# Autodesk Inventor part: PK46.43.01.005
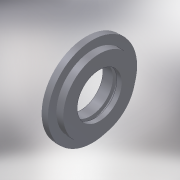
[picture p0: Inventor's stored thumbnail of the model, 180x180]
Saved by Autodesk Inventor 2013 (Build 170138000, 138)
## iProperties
Shininess: 64.0
Length Units: 11269
Angle Units: 11279
Time Units: 11290
Mass Units: 11283
Length Display Precision: 3
Angle Display Precision: 2
Compacted: True
Part Number: PK46.43.01.005
Document SubType Name: Modeling
Created: 2004-11
Material: Сталь высокопрочная низколегированная
Designer: ELarisa
Manufacturer: Standard
Standards Organization: Custom
Density: 7.84 g/cm^3
Density: 0.0
Volumn: 0.0
Area: 0.0
PropertySet Name: Model Information
Control State: 0
Master: False
Checked Out: False
Checked Out Date: 2008-10-09
Last Check In Date: 2008-10-09
Author: ELarisa
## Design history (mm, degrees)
sketch "Эскиз1"
  geometry: L1 (-25.184, 0.049)-(-25.184, 45.049); L2 (-25.184, 45.049)-(-16.184, 45.049); L3 (-16.184, 45.049)-(-16.184, 71.049); L4 (-16.184, 71.049)-(-6.184, 71.049); L5 (-6.184, 71.049)-(-6.184, 57.549); L6 (-6.184, 57.549)-(4.816, 57.549); L7 (4.816, 57.549)-(4.816, 0.049); L8 (4.816, 0.049)-(-25.184, 0.049); L9 (-25.184, 35.549)-(-9.184, 35.549); L10 (-9.184, 35.549)-(-9.184, 42.099); L11 (-9.184, 42.099)-(-2.884, 42.099); L12 (-2.884, 42.099)-(-2.884, 35.549); L13 (-2.884, 35.549)-(4.816, 35.549)
  constraints: 26 end point, 9 parallel, 3 perpendicular, 2 point on line, 1 collinear, 1 vertical
  dimensions: "d0" = 30 distance of L7.end L1.start; "d1" = 14 distance between parallel lines of L7 L10; "d2" = 6.3 distance of L10.end L11.end; "d3" = 42.05 distance between parallel lines of L8 L11; "d4" = 71 distance between parallel lines of L8 L4; "d5" = 57.5 distance between parallel lines of L8 L6; "d6" = 45 distance between parallel lines of L8 L2; "d7" = 35.5 distance between parallel lines of L8 L13; "d8" = 9 distance of L1.end L2.end; "d9" = 19 distance between parallel lines of L5 L1
revolve "Вращение1" sketch "Эскиз1" stored, may be unused: angle "d10" = 90 deg
body "Solid1"
